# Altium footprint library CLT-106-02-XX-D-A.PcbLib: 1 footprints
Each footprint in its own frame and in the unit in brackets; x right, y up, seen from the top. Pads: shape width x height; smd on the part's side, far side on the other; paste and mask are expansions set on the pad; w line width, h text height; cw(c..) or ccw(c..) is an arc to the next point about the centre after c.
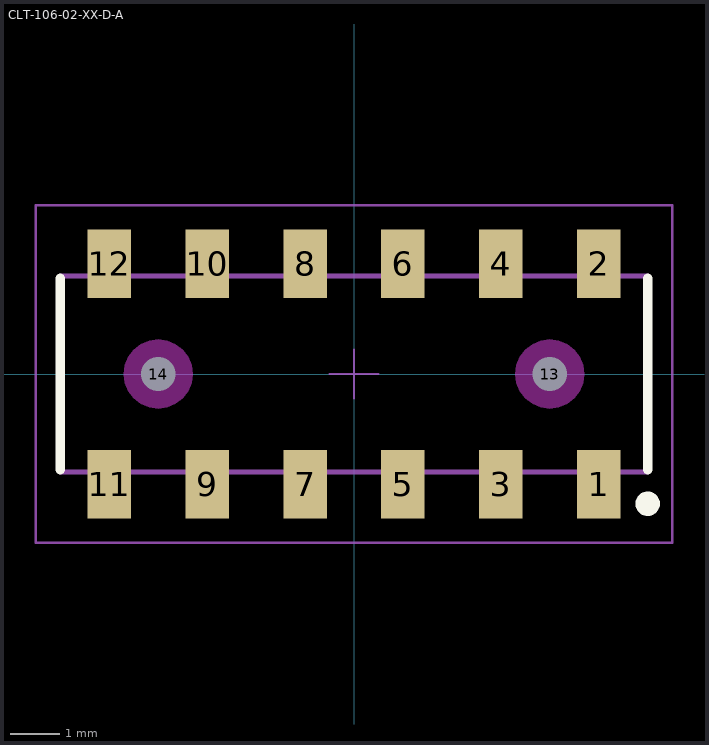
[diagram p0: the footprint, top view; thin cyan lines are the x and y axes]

## CLT-106-02-XX-D-A [mm] "2.00mm pitch, 14 pin, header; low profile, w/alignment pins"
height 2.13
pads (14):
  rect 0.89x1.4 smd mask+0: 1(5,-2.25) 2(5,2.25) 3(3,-2.25) 4(3,2.25) 5(1,-2.25) 6(1,2.25) 7(-1,-2.25) 8(-1,2.25) 9(-3,-2.25) 10(-3,2.25) 11(-5,-2.25) 12(-5,2.25)
  round 0.5 hole 0.7 unplated mask+0: 13(4,0) 14(-4,0)
Top Overlay:
  circle w0.25: c6,-2.65 r0.125
  lines w0.2: -6,-1.95 -6,1.95 ; 6,-1.95 6,1.95
Keep-Out Layer:
  pour cut-out: 4.706,0 4.682,0.183 4.611,0.353 4.499,0.499 4.353,0.611 4.183,0.682 4,0.706 3.817,0.682 3.647,0.611 3.501,0.499 3.389,0.353 3.318,0.183 3.294,0 3.318,-0.183 3.389,-0.353 3.501,-0.499 3.647,-0.611 3.817,-0.682 4,-0.706 4.183,-0.682 4.353,-0.611 4.499,-0.499 4.611,-0.353 4.682,-0.183
  pour cut-out: -3.294,0 -3.318,0.183 -3.389,0.353 -3.501,0.499 -3.647,0.611 -3.817,0.682 -4,0.706 -4.183,0.682 -4.353,0.611 -4.499,0.499 -4.611,0.353 -4.682,0.183 -4.706,0 -4.682,-0.183 -4.611,-0.353 -4.499,-0.499 -4.353,-0.611 -4.183,-0.682 -4,-0.706 -3.817,-0.682 -3.647,-0.611 -3.501,-0.499 -3.389,-0.353 -3.318,-0.183
Mechanical 12:
  lines w0.001: -6,-2 -6,2 6,2 6,-2 -6,-2
Mechanical 13:
  lines w0.1: -6,-2 -6,2 6,2 6,-2 -6,-2
  text ".Designator" at 0.254,0.254 h1.52
Mechanical 15:
  lines w0.05: -0.5,0 0.5,0 ; 0,-0.5 0,0.5 ; -6.5,-3.45 -6.5,3.45 6.5,3.45 6.5,-3.45 -6.5,-3.45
